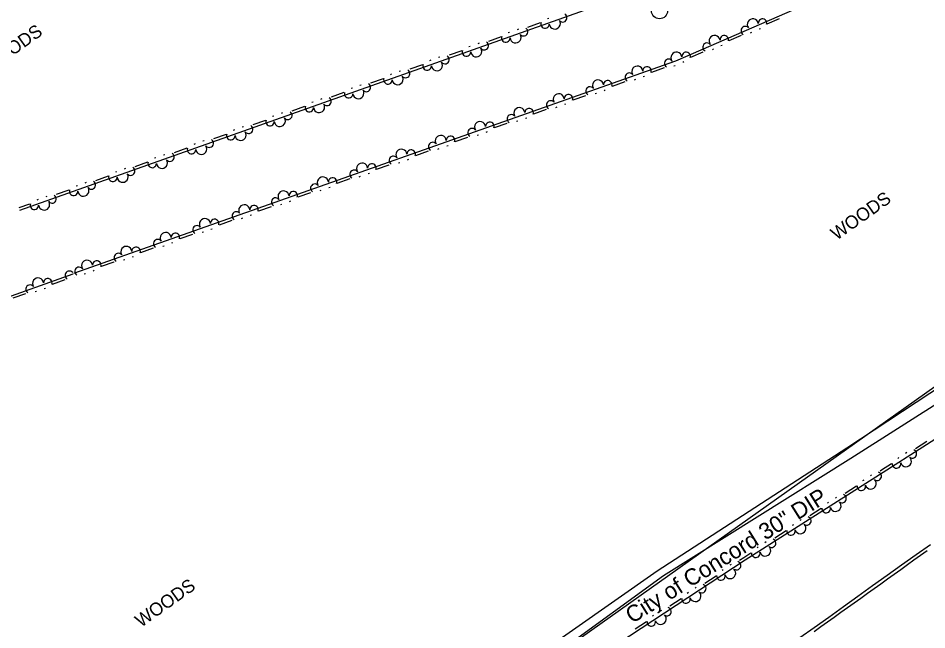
# Model space of a CAD drawing. Extents: x 1577032 to 1581865, y 611492 to 615011.
# Drawn here: x 1578202.1 to 1578479.3, y 612392.5 to 612579.2 of the extents above; entities that cross this region are included whole.
import ezdxf

# ---------------------------------------------------------------- set-up
doc = ezdxf.new("R2010")
doc.units = 0
for name, color, linetype in [('Exist Right of Way Line', 7, 'Continuous'), ('Exist Roads EOP', 7, 'Continuous'), ('Exist Roads EOT', 7, 'Continuous'), ('Exist Utilities Power Pole CELL', 7, 'Continuous'), ('Exist Utilities Telephone UG FO SUE LOS B', 7, 'Continuous'), ('Exist Utilities Water UG Line SUE LOS B', 7, 'Continuous'), ('Exist Utilities Water UG Line SUE LOS B Text', 7, 'Continuous'), ('Exist Vegetation Woods Line Text', 7, 'Continuous'), ('Old_Level_11', 7, 'Continuous')]:
    doc.layers.add(name, color=color, linetype=linetype)

msp = doc.modelspace()

# ---------------------------------------------------------------- linework, layer by layer
at = {"layer": 'Exist Right of Way Line'}
msp.add_lwpolyline([(1578124.38, 612213.06), (1579205.66, 612980.92)], dxfattribs=at)
at = {"layer": 'Exist Roads EOP'}
msp.add_lwpolyline([(1578480.36, 612418.44), (1578475.98, 612415.33), (1578471.58, 612412.19), (1578467.16, 612409.04), (1578462.72, 612405.86), (1578458.26, 612402.66), (1578453.8, 612399.46), (1578449.36, 612396.28), (1578444.94, 612393.12), (1578440.55, 612389.98)], dxfattribs=at)
at = {"layer": 'Exist Roads EOT'}
msp.add_lwpolyline([(1578479.4, 612416.63), (1578477.37, 612415.17), (1578475.34, 612413.72), (1578473.31, 612412.26), (1578471.28, 612410.81), (1578469.25, 612409.36), (1578467.22, 612407.9), (1578465.19, 612406.45), (1578463.16, 612404.99), (1578461.14, 612403.54), (1578459.11, 612402.08), (1578457.08, 612400.63), (1578455.05, 612399.18), (1578453.02, 612397.72), (1578450.99, 612396.27), (1578448.96, 612394.81), (1578446.93, 612393.36), (1578444.9, 612391.9)], dxfattribs=at)
at = {"layer": 'Exist Utilities Power Pole CELL'}
msp.add_circle((1578397.73, 612581.45), 2.45, dxfattribs=at)
at = {"layer": 'Exist Utilities Telephone UG FO SUE LOS B'}
msp.add_lwpolyline([(1578195.73, 612250.34), (1578241.59, 612286.54), (1578291.86, 612328.33), (1578346.38, 612374.92), (1578396.97, 612410.49), (1578454.86, 612448.05), (1578513.8, 612486.88), (1578570.79, 612520.18), (1578660.13, 612580.57), (1578739.65, 612636.41), (1578799.35, 612673.77), (1578835.75, 612699.17), (1578865.6, 612719.98), (1578923.89, 612761.36), (1578953.65, 612786.53), (1578992.35, 612823.36), (1579016.04, 612847.4), (1579030.15, 612863.93), (1579038.32, 612877.78)], dxfattribs=at)
at = {"layer": 'Exist Utilities Water UG Line SUE LOS B'}
for p, q in [((1578456.08, 612444.84), (1578516.14, 612483.13)), ((1578398.94, 612409.07), (1578456.08, 612444.84)), ((1578347.91, 612371.98), (1578398.94, 612409.07))]:
    msp.add_line(p, q, dxfattribs=at)
at = {"layer": 'Old_Level_11'}
msp.add_line((1578108.33, 612461.99), (1578218.92, 612501.12), dxfattribs=at)
for points in [[(1578854.39, 612741.35), (1578805.77, 612755.29), (1578776.22, 612749.53), (1578748.88, 612739.86), (1578397.75, 612589.78), (1578202.57, 612520.47)], [(1578219.14, 612501.33), (1578402.75, 612566.18), (1578724.72, 612706.14), (1578817.97, 612709.56)], [(1578817.97, 612709.56), (1578809.14, 612701.87), (1578766.25, 612667.71), (1578729.93, 612641.39), (1578711, 612629.29), (1578666.02, 612599.72), (1578626.26, 612569.19), (1578597.37, 612539.75), (1578558.5, 612501.79), (1578537.75, 612486.32), (1578502.24, 612463.66), (1578465.91, 612440.49), (1578423.86, 612413.78), (1578371.1, 612378.99), (1578339.9, 612361.7)], [(1578361.37, 612577.73), (1578357.51, 612576.36)], [(1578363.94, 612579.08), (1578363.56, 612578.94)], [(1578430.6, 612577.4), (1578434.36, 612579.03)], [(1578351.96, 612574.82), (1578351.58, 612574.69)], [(1578354.67, 612575.79), (1578354.28, 612575.65)], [(1578425.5, 612574.73), (1578425.88, 612574.89)], [(1578428.13, 612575.88), (1578428.51, 612576.04)], [(1578342.69, 612571.53), (1578342.3, 612571.39)], [(1578349.39, 612573.48), (1578345.53, 612572.1)], [(1578418.94, 612572.33), (1578422.7, 612573.96)], [(1578337.41, 612569.22), (1578333.55, 612567.85)], [(1578339.98, 612570.57), (1578339.6, 612570.43)], [(1578407.28, 612567.26), (1578411.04, 612568.89)], [(1578413.84, 612569.66), (1578414.22, 612569.83)], [(1578416.47, 612570.81), (1578416.85, 612570.97)], [(1578328, 612566.32), (1578327.62, 612566.18)], [(1578330.71, 612567.28), (1578330.32, 612567.14)], [(1578404.81, 612565.74), (1578405.19, 612565.9)], [(1578318.72, 612563.02), (1578318.34, 612562.88)], [(1578325.43, 612564.97), (1578321.57, 612563.6)], [(1578395.36, 612562.7), (1578399.23, 612564.07)], [(1578402.07, 612564.64), (1578402.46, 612564.77)], [(1578313.45, 612560.71), (1578309.59, 612559.34)], [(1578316.02, 612562.06), (1578315.63, 612561.93)], [(1578390.08, 612560.4), (1578390.47, 612560.54)], [(1578392.79, 612561.36), (1578393.18, 612561.5)], [(1578304.04, 612557.81), (1578303.65, 612557.67)], [(1578306.75, 612558.77), (1578306.36, 612558.63)], [(1578383.37, 612558.47), (1578387.24, 612559.83)], [(1578301.47, 612556.46), (1578297.61, 612555.09)], [(1578371.38, 612554.23), (1578375.25, 612555.6)], [(1578378.1, 612556.17), (1578378.48, 612556.31)], [(1578380.8, 612557.13), (1578381.19, 612557.26)], [(1578289.49, 612552.21), (1578285.63, 612550.83)], [(1578292.06, 612553.55), (1578291.67, 612553.42)], [(1578294.76, 612554.51), (1578294.38, 612554.38)], [(1578366.11, 612551.94), (1578366.5, 612552.07)], [(1578368.81, 612552.89), (1578369.2, 612553.03)], [(1578280.08, 612549.3), (1578279.69, 612549.16)], [(1578282.79, 612550.26), (1578282.4, 612550.12)], [(1578359.4, 612550), (1578363.26, 612551.37)], [(1578277.51, 612547.95), (1578273.65, 612546.58)], [(1578347.41, 612545.77), (1578351.28, 612547.13)], [(1578354.12, 612547.7), (1578354.51, 612547.84)], [(1578356.83, 612548.66), (1578357.21, 612548.79)], [(1578265.53, 612543.7), (1578261.67, 612542.33)], [(1578268.1, 612545.05), (1578267.71, 612544.91)], [(1578270.8, 612546.01), (1578270.42, 612545.87)], [(1578344.84, 612544.42), (1578345.23, 612544.56)], [(1578258.82, 612541.75), (1578258.44, 612541.62)], [(1578335.42, 612541.53), (1578339.29, 612542.9)], [(1578342.13, 612543.47), (1578342.52, 612543.6)], [(1578253.55, 612539.45), (1578249.69, 612538.07)], [(1578256.12, 612540.79), (1578255.73, 612540.66)], [(1578323.44, 612537.3), (1578327.3, 612538.66)], [(1578330.15, 612539.23), (1578330.53, 612539.37)], [(1578332.85, 612540.19), (1578333.24, 612540.33)], [(1578244.14, 612536.54), (1578243.75, 612536.4)], [(1578246.84, 612537.5), (1578246.46, 612537.36)], [(1578320.87, 612535.96), (1578321.25, 612536.09)], [(1578234.86, 612533.25), (1578234.48, 612533.11)], [(1578241.57, 612535.19), (1578237.7, 612533.82)], [(1578311.45, 612533.06), (1578315.31, 612534.43)], [(1578318.16, 612535), (1578318.54, 612535.14)], [(1578229.59, 612530.94), (1578225.72, 612529.56)], [(1578232.16, 612532.28), (1578231.77, 612532.15)], [(1578299.46, 612528.83), (1578303.33, 612530.2)], [(1578306.17, 612530.77), (1578306.56, 612530.9)], [(1578308.88, 612531.72), (1578309.26, 612531.86)], [(1578220.18, 612528.03), (1578219.79, 612527.89)], [(1578222.88, 612528.99), (1578222.5, 612528.85)], [(1578296.89, 612527.49), (1578297.28, 612527.63)], [(1578210.9, 612524.74), (1578210.52, 612524.6)], [(1578217.61, 612526.68), (1578213.74, 612525.31)], [(1578287.47, 612524.6), (1578291.34, 612525.96)], [(1578294.18, 612526.53), (1578294.57, 612526.67)], [(1578205.63, 612522.43), (1578202.29, 612521.24)], [(1578208.2, 612523.78), (1578207.81, 612523.64)], [(1578275.49, 612520.36), (1578279.35, 612521.73)], [(1578282.2, 612522.3), (1578282.58, 612522.43)], [(1578284.9, 612523.25), (1578285.29, 612523.39)], [(1578272.91, 612519.02), (1578273.3, 612519.16)], [(1578263.5, 612516.13), (1578267.37, 612517.49)], [(1578270.21, 612518.06), (1578270.6, 612518.2)], [(1578251.51, 612511.89), (1578255.38, 612513.26)], [(1578258.22, 612513.83), (1578258.61, 612513.97)], [(1578260.93, 612514.79), (1578261.31, 612514.92)], [(1578248.94, 612510.55), (1578249.33, 612510.69)], [(1578239.52, 612507.66), (1578243.39, 612509.03)], [(1578246.23, 612509.6), (1578246.62, 612509.73)], [(1578234.24, 612505.36), (1578234.63, 612505.5)], [(1578236.95, 612506.32), (1578237.34, 612506.45)], [(1578224.97, 612502.08), (1578225.35, 612502.22)], [(1578227.54, 612503.43), (1578231.4, 612504.79)], [(1578212.61, 612498.01), (1578216.47, 612499.38)], [(1578219.3, 612499.94), (1578219.31, 612499.95)], [(1578222.26, 612501.13), (1578222.64, 612501.26)], [(1578210.04, 612496.67), (1578210.43, 612496.81)], [(1578200.62, 612493.77), (1578204.49, 612495.14)], [(1578207.33, 612495.71), (1578207.72, 612495.85)], [(1578479.25, 612449.97), (1578475.79, 612447.76)], [(1578470.73, 612445.02), (1578470.38, 612444.8)], [(1578473.15, 612446.56), (1578472.8, 612446.34)], [(1578468.53, 612443.13), (1578465.47, 612441.18), (1578465.07, 612440.92)], [(1578462.43, 612439.73), (1578462.09, 612439.51)], [(1578457.8, 612436.31), (1578454.34, 612434.11)], [(1578460.01, 612438.19), (1578459.66, 612437.97)], [(1578451.7, 612432.92), (1578451.35, 612432.7)], [(1578449.28, 612431.38), (1578448.93, 612431.16)], [(1578447.07, 612429.49), (1578443.61, 612427.29)], [(1578438.54, 612424.56), (1578438.2, 612424.34)], [(1578440.97, 612426.1), (1578440.62, 612425.88)], [(1578436.34, 612422.68), (1578432.88, 612420.48)], [(1578430.23, 612419.29), (1578429.89, 612419.07)], [(1578427.81, 612417.75), (1578427.46, 612417.53)], [(1578425.61, 612415.86), (1578423.42, 612414.47), (1578422.15, 612413.63)], [(1578417.13, 612410.82), (1578416.79, 612410.59)], [(1578419.53, 612412.4), (1578419.18, 612412.17)], [(1578414.96, 612408.89), (1578411.53, 612406.64)], [(1578408.91, 612405.4), (1578408.57, 612405.17)], [(1578406.52, 612403.82), (1578406.17, 612403.59)], [(1578404.35, 612401.89), (1578400.92, 612399.64)], [(1578395.9, 612396.82), (1578395.56, 612396.59)], [(1578398.3, 612398.4), (1578397.96, 612398.17)], [(1578393.73, 612394.89), (1578390.31, 612392.64)]]:
    msp.add_lwpolyline(points, dxfattribs=at)
for centre, radius, start, end in [((1578368.22, 612579.29), 1.3, 217.984, 58.7806), ((1578362.81, 612577.37), 1.3, 160.3175, 1.1141), ((1578365.79, 612577.56), 1.69, 185.5128, 33.5853), ((1578426.19, 612577.27), 1.69, 9.4589, 217.5314), ((1578429.15, 612577.66), 1.3, 344.2636, 185.0602), ((1578353.81, 612573.3), 1.69, 185.5128, 33.5853), ((1578356.24, 612575.04), 1.3, 217.984, 58.7806), ((1578423.88, 612575.37), 1.3, 41.9301, 242.7266), ((1578344.26, 612570.78), 1.3, 217.984, 58.7806), ((1578350.83, 612573.12), 1.3, 160.3175, 1.1141), ((1578412.22, 612570.3), 1.3, 41.9301, 242.7266), ((1578414.53, 612572.2), 1.69, 9.4589, 217.5314), ((1578417.49, 612572.59), 1.3, 344.2636, 185.0602), ((1578338.85, 612568.86), 1.3, 160.3175, 1.1141), ((1578341.83, 612569.05), 1.69, 185.5128, 33.5853), ((1578402.87, 612567.13), 1.69, 9.4589, 217.5314), ((1578405.83, 612567.52), 1.3, 344.2636, 185.0602), ((1578332.28, 612566.53), 1.3, 217.984, 58.7806), ((1578400.5, 612565.39), 1.3, 37.8884, 238.6849), ((1578320.3, 612562.28), 1.3, 217.984, 58.7806), ((1578326.87, 612564.61), 1.3, 160.3175, 1.1141), ((1578329.85, 612564.8), 1.69, 185.5128, 33.5853), ((1578390.95, 612562.88), 1.69, 5.4172, 213.4897), ((1578393.93, 612563.07), 1.3, 340.2219, 181.0185), ((1578314.89, 612560.35), 1.3, 160.3175, 1.1141), ((1578317.87, 612560.54), 1.69, 185.5128, 33.5853), ((1578378.96, 612558.65), 1.69, 5.4172, 213.4897), ((1578388.51, 612561.15), 1.3, 37.8884, 238.6849), ((1578308.32, 612558.02), 1.3, 217.984, 58.7806), ((1578376.53, 612556.92), 1.3, 37.8884, 238.6849), ((1578381.94, 612558.83), 1.3, 340.2219, 181.0185), ((1578296.34, 612553.77), 1.3, 217.984, 58.7806), ((1578302.91, 612556.1), 1.3, 160.3175, 1.1141), ((1578305.89, 612556.29), 1.69, 185.5128, 33.5853), ((1578366.97, 612554.42), 1.69, 5.4172, 213.4897), ((1578369.95, 612554.6), 1.3, 340.2219, 181.0185), ((1578290.93, 612551.85), 1.3, 160.3175, 1.1141), ((1578293.91, 612552.03), 1.69, 185.5128, 33.5853), ((1578364.54, 612552.69), 1.3, 37.8884, 238.6849), ((1578284.36, 612549.51), 1.3, 217.984, 58.7806), ((1578352.55, 612548.45), 1.3, 37.8884, 238.6849), ((1578354.98, 612550.18), 1.69, 5.4172, 213.4897), ((1578357.96, 612550.36), 1.3, 340.2219, 181.0185), ((1578278.94, 612547.59), 1.3, 160.3175, 1.1141), ((1578281.92, 612547.78), 1.69, 185.5128, 33.5853), ((1578343, 612545.95), 1.69, 5.4172, 213.4897), ((1578345.98, 612546.13), 1.3, 340.2219, 181.0185), ((1578266.96, 612543.34), 1.3, 160.3175, 1.1141), ((1578269.94, 612543.53), 1.69, 185.5128, 33.5853), ((1578272.38, 612545.26), 1.3, 217.984, 58.7806), ((1578340.56, 612544.22), 1.3, 37.8884, 238.6849), ((1578260.39, 612541.01), 1.3, 217.984, 58.7806), ((1578328.58, 612539.98), 1.3, 37.8884, 238.6849), ((1578331.01, 612541.71), 1.69, 5.4172, 213.4897), ((1578333.99, 612541.9), 1.3, 340.2219, 181.0185), ((1578254.98, 612539.08), 1.3, 160.3175, 1.1141), ((1578257.96, 612539.27), 1.69, 185.5128, 33.5853), ((1578319.02, 612537.48), 1.69, 5.4172, 213.4897), ((1578322, 612537.66), 1.3, 340.2219, 181.0185), ((1578245.98, 612535.02), 1.69, 185.5128, 33.5853), ((1578248.41, 612536.75), 1.3, 217.984, 58.7806), ((1578316.59, 612535.75), 1.3, 37.8884, 238.6849), ((1578236.43, 612532.5), 1.3, 217.984, 58.7806), ((1578243, 612534.83), 1.3, 160.3175, 1.1141), ((1578304.6, 612531.52), 1.3, 37.8884, 238.6849), ((1578307.03, 612533.25), 1.69, 5.4172, 213.4897), ((1578310.01, 612533.43), 1.3, 340.2219, 181.0185), ((1578231.02, 612530.58), 1.3, 160.3175, 1.1141), ((1578234, 612530.76), 1.69, 185.5128, 33.5853), ((1578295.05, 612529.01), 1.69, 5.4172, 213.4897), ((1578298.03, 612529.19), 1.3, 340.2219, 181.0185), ((1578222.02, 612526.51), 1.69, 185.5128, 33.5853), ((1578224.45, 612528.24), 1.3, 217.984, 58.7806), ((1578292.61, 612527.28), 1.3, 37.8884, 238.6849), ((1578212.47, 612523.99), 1.3, 217.984, 58.7806), ((1578219.04, 612526.32), 1.3, 160.3175, 1.1141), ((1578280.63, 612523.05), 1.3, 37.8884, 238.6849), ((1578283.06, 612524.78), 1.69, 5.4172, 213.4897), ((1578286.04, 612524.96), 1.3, 340.2219, 181.0185), ((1578207.06, 612522.07), 1.3, 160.3175, 1.1141), ((1578210.04, 612522.26), 1.69, 185.5128, 33.5853), ((1578271.07, 612520.54), 1.69, 5.4172, 213.4897), ((1578274.05, 612520.73), 1.3, 340.2219, 181.0185), ((1578268.64, 612518.81), 1.3, 37.8884, 238.6849), ((1578259.08, 612516.31), 1.69, 5.4172, 213.4897), ((1578262.06, 612516.49), 1.3, 340.2219, 181.0185), ((1578247.1, 612512.08), 1.69, 5.4172, 213.4897), ((1578250.08, 612512.26), 1.3, 340.2219, 181.0185), ((1578256.65, 612514.58), 1.3, 37.8884, 238.6849), ((1578244.66, 612510.35), 1.3, 37.8884, 238.6849), ((1578235.11, 612507.84), 1.69, 5.4172, 213.4897), ((1578238.09, 612508.02), 1.3, 340.2219, 181.0185), ((1578223.12, 612503.61), 1.69, 5.4172, 213.4897), ((1578226.1, 612503.79), 1.3, 340.2219, 181.0185), ((1578232.68, 612506.11), 1.3, 37.8884, 238.6849), ((1578220.69, 612501.88), 1.3, 37.8884, 238.6849), ((1578208.19, 612498.19), 1.69, 5.4494, 213.5219), ((1578211.17, 612498.38), 1.3, 340.2541, 181.0507), ((1578217.75, 612500.7), 1.3, 37.9206, 238.7172), ((1578205.76, 612496.46), 1.3, 37.9206, 238.7172), ((1578474.85, 612446.19), 1.3, 230.9717, 71.7683), ((1578472.87, 612443.95), 1.69, 198.5005, 46.573), ((1578470.01, 612443.1), 1.3, 173.3053, 14.1018), ((1578462.15, 612437.12), 1.69, 198.3795, 46.4519), ((1578464.13, 612439.35), 1.3, 230.8506, 71.6472), ((1578459.28, 612436.27), 1.3, 173.1842, 13.9807), ((1578453.4, 612432.54), 1.3, 230.8506, 71.6472), ((1578451.41, 612430.31), 1.69, 198.3795, 46.4519), ((1578448.55, 612429.46), 1.3, 173.1842, 13.9807), ((1578440.68, 612423.49), 1.69, 198.3795, 46.4519), ((1578442.66, 612425.72), 1.3, 230.8506, 71.6472), ((1578437.82, 612422.64), 1.3, 173.1842, 13.9807), ((1578431.93, 612418.91), 1.3, 230.8506, 71.6472), ((1578427.09, 612415.83), 1.3, 173.1842, 13.9807), ((1578429.95, 612416.68), 1.69, 198.3795, 46.4519), ((1578419.28, 612409.78), 1.69, 199.3667, 47.4392), ((1578421.23, 612412.05), 1.3, 231.8379, 72.6345), ((1578416.44, 612408.89), 1.3, 174.1715, 14.968), ((1578410.62, 612405.05), 1.3, 231.8379, 72.6345), ((1578408.67, 612402.78), 1.69, 199.3667, 47.4392), ((1578405.82, 612401.89), 1.3, 174.1715, 14.968), ((1578398.06, 612395.78), 1.69, 199.3667, 47.4392), ((1578400, 612398.05), 1.3, 231.8379, 72.6345), ((1578395.21, 612394.89), 1.3, 174.1715, 14.968)]:
    msp.add_arc(centre, radius, start, end, dxfattribs=at)

# ---------------------------------------------------------------- texts
at = {"layer": 'Exist Utilities Water UG Line SUE LOS B Text'}
msp.add_text('City of Concord 30" DIP', height=5, rotation=32.0434, dxfattribs=at).set_placement((1578389.36, 612394.23))
at = {"layer": 'Exist Vegetation Woods Line Text'}
for p in [(1578192.93, 612562.27), (1578451.75, 612511.22), (1578239.59, 612393.06)]:
    msp.add_text('WOODS', height=4, rotation=35.38, dxfattribs=at).set_placement(p)

doc.saveas('drawing.dxf')
